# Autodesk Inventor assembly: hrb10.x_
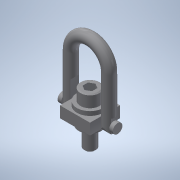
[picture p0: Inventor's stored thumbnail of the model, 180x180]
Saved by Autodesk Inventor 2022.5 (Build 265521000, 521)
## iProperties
Part Number: hrb10.x_
Material: 一般
Document SubType Name: Assembly
Designer: ImaoCorp
Sending System: SOLIDWORKS 2017-2017317
MC: AMD64
MC_MODEL: Intel64 Family 6 Model 60 Stepping 3, GenuineIntel
OS: Windows_NT
FRU: Parasolid Version 29.0, build 201,  4-17-2017
FORMAT: text
GUISE: transmit
KEY: hrb10
FILE: hrb10.x_t
DATE: Mon Jul 01 17:38:48 2019
Author: ImaoCorp
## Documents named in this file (3)
- X:\14_SW2022-Inv2022\00_全2023-1023新製品(TCC)まで\h\hrb10\HRB10.iam
- X:\14_SW2022-Inv2022\00_全2023-1023新製品(TCC)まで\h\hrb10\hrb10_01.ipt
- X:\14_SW2022-Inv2022\00_全2023-1023新製品(TCC)まで\h\hrb10\hrb10_02.ipt
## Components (2 placed, 2 different names)
1. hrb10_01
2. hrb10_02
